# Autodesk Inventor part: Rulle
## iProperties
Shininess: 64.0
Angle Display Precision: 2
Document Length Units: 11269
Document Angle Units: 11279
Document Time Units: 11290
Document Mass Units: 11283
Document Length Units Precision: 3
Document Angle Units Precision: 2
Created: 2001-12
Part Number: Rulle
Material: Aluminum-6061
Document SubType Name: Modeling
Designer: Tobben
Density: 1 g/cm^3
Density: 0.0
Volumn: 0.0
Area: 0.0
PropertySet Name: Model Information
Control State: 0
Master: False
Checked Out: False
Author: Tobben
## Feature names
1. Extrusion1
